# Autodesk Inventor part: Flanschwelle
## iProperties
Created: 2005-12
Part Number: Flanschwelle
Document SubType Name: Modeling
Designer: Sascha
Manufacturer: Standard
Standards Organization: Custom
Author: Sascha
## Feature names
1. Drehung1 [Revolution]
2. Fase1 [Chamfer]
3. Rundung1 [Fillet]
4. Fase2 [Chamfer]
5. Fase3 [Chamfer]
6. Fase4 [Chamfer]
7. Bohrung1 [Hole]
8. Runde Anordnung1 [Circular Pattern]
9. Bohrung2 [Hole]
10. Extrusion2
